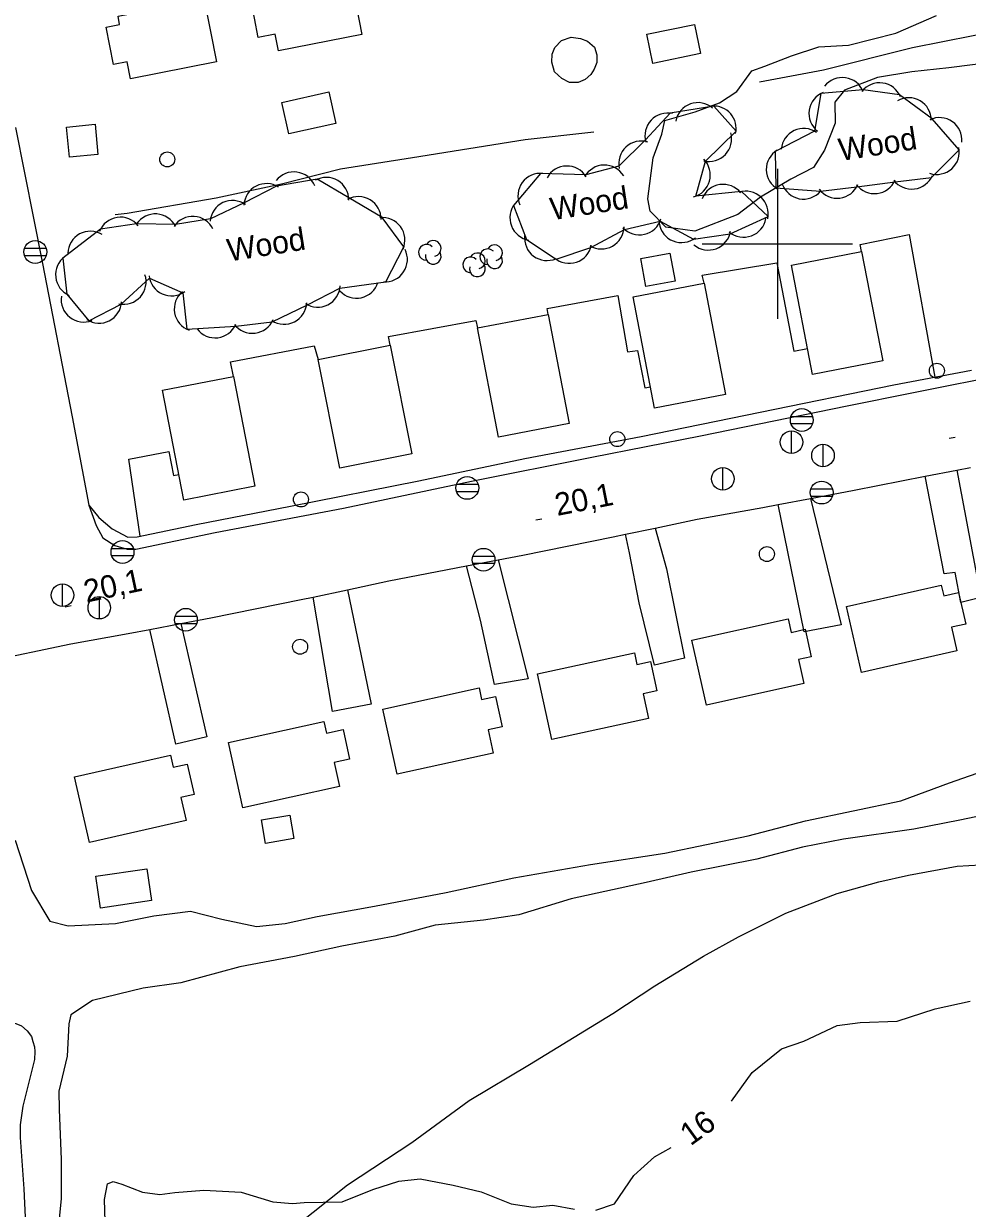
# Model space of a CAD drawing. Extents: x 646142 to 649934, y 5874075 to 5876351.
# Drawn here: x 646899.7 to 647025.3, y 5875071.6 to 5875229.3 of the extents above; entities that cross this region are included whole.
import ezdxf

# ---------------------------------------------------------------- set-up
doc = ezdxf.new("R2010")
doc.units = 0
for name, color, linetype in [('Niveau 1', 7, 'Continuous'), ('Niveau 19', 7, 'Continuous'), ('Niveau 2', 7, 'Continuous'), ('Niveau 21', 7, 'Continuous'), ('Niveau 22', 7, 'Continuous'), ('Niveau 3', 7, 'Continuous'), ('Niveau 31', 7, 'Continuous'), ('Niveau 36', 7, 'Continuous'), ('Niveau 4', 7, 'Continuous'), ('Niveau 44', 7, 'Continuous'), ('Niveau 61', 7, 'Continuous')]:
    doc.layers.add(name, color=color, linetype=linetype)

msp = doc.modelspace()

# ---------------------------------------------------------------- linework, layer by layer
at = {"layer": 'Niveau 1'}
for points in [[(647029.14, 5875224.24), (647022.82, 5875223.41), (647017.88, 5875222.92), (647013.33, 5875222.14), (647008.92, 5875220.45), (647007.66, 5875218.87), (647007.68, 5875216.07), (647006.29, 5875212.47), (647004.82, 5875210.18), (647001.78, 5875208.61), (646997.74, 5875206.22), (646994.72, 5875203.91), (646989, 5875201.67), (646985.16, 5875202.23), (646983.04, 5875204.37), (646982.75, 5875205.99), (646983.47, 5875211.45), (646984.62, 5875214.62), (646985, 5875216.44), (646989.06, 5875217.56), (646992.31, 5875218.76), (646994.61, 5875220.3), (646996.61, 5875223.01), (646998.32, 5875223.67), (647001.9, 5875225.02), (647005.5, 5875226.21), (647009.48, 5875226.47), (647015.79, 5875228.04), (647021.2, 5875230.42)], [(646898.52, 5875120.6), (646900.69, 5875113.91), (646903.14, 5875109.82), (646905.56, 5875109.21), (646911.89, 5875109.53), (646917, 5875110.56), (646921.86, 5875111.16), (646926.05, 5875110.08), (646930.63, 5875109.1), (646934.48, 5875109.52), (646938.73, 5875110.45), (646946.37, 5875111.84), (646955.91, 5875113.65), (646964.92, 5875115.62), (646975.1, 5875117.38), (646985.01, 5875118.89), (646996.1, 5875121.17), (647003.72, 5875123.19), (647016.42, 5875125.84), (647022.92, 5875128.24), (647028.37, 5875130.17)]]:
    msp.add_lwpolyline(points, dxfattribs=at)
at = {"layer": 'Niveau 19'}
for points in [[(647011.2, 5875198.98), (647011, 5875199.92), (647017.53, 5875201.24), (647020.94, 5875182.27)], [(646990.23, 5875194.75), (646989.97, 5875195.84), (646999.94, 5875197.47), (647002.21, 5875185.73), (647004.01, 5875186.07)], [(646969.5, 5875190.6), (646969.37, 5875191.4), (646978.75, 5875193.12), (646980.03, 5875185.62), (646981.37, 5875185.81), (646982.33, 5875180.84), (646983.09, 5875180.97)], [(646948.43, 5875186.51), (646948.21, 5875187.65), (646959.83, 5875189.79), (646960.09, 5875188.8)], [(646927.57, 5875182.36), (646927.17, 5875184.29), (646938.31, 5875186.44), (646938.88, 5875184.6)], [(646915.15, 5875161.07), (646913.67, 5875171.35), (646918.98, 5875172.34), (646919.61, 5875169.17), (646920.32, 5875169.28)], [(647023.9, 5875169.89), (647027.1, 5875152.94), (647024.43, 5875152.24), (647023.66, 5875156.25), (647022.19, 5875156.07), (647019.67, 5875169.06)], [(647004.4, 5875166.12), (647008.51, 5875149.28), (647003.57, 5875148.33), (647000.11, 5875165.31)], [(646983.72, 5875162.16), (646985.22, 5875156.75), (646987.65, 5875144.84), (646983.63, 5875143.89), (646981.59, 5875152.19), (646980.29, 5875158.88), (646979.76, 5875161.33)], [(646962.82, 5875157.94), (646966.83, 5875142.11), (646962.33, 5875141.33), (646960.49, 5875149.89), (646958.63, 5875157.14)], [(646942.78, 5875153.96), (646945.93, 5875138.71), (646940.77, 5875137.73), (646938.19, 5875152.98)], [(646920.56, 5875149.46), (646924.04, 5875134.36), (646919.91, 5875133.39), (646916.47, 5875148.68)], [(646897.27, 5875096.49), (646898.61, 5875096.2), (646899.37, 5875095.89), (646900.11, 5875095.25), (646900.68, 5875094.48), (646900.89, 5875093.83), (646901.11, 5875093.12), (646901.13, 5875092.5), (646901.1, 5875091.43), (646899.53, 5875085.21), (646899.17, 5875082.7), (646899.2, 5875081.01), (646899.68, 5875074.19), (646900.15, 5875063.78), (646900.5, 5875054.57), (646900.55, 5875049.06), (646899.93, 5875043.52), (646897.51, 5875037.07), (646896.53, 5875036.24), (646895.1, 5875035.55), (646893.95, 5875035.43), (646892.74, 5875035.5), (646891.78, 5875035.88), (646889.11, 5875036.54)]]:
    msp.add_lwpolyline(points, dxfattribs=at)
at = {"layer": 'Niveau 2'}
for points in [[(647028.54, 5875124.16), (647024.28, 5875123.27), (647018.18, 5875122.09), (647008.8, 5875120.76), (647003.33, 5875119.7), (646997.28, 5875118.07), (646988.51, 5875116.34), (646982.55, 5875115), (646972.55, 5875112.8), (646965.56, 5875110.67), (646960.87, 5875109.97), (646954.44, 5875109.28), (646949.09, 5875107.82), (646942.01, 5875106.49), (646935.73, 5875105.14), (646928.42, 5875103.73), (646920.56, 5875101.61), (646915.58, 5875100.89), (646908.81, 5875099.25), (646905.92, 5875097.35), (646905.65, 5875096.18)], [(646993.89, 5875085.87), (646996.64, 5875089.69), (647000.54, 5875092.83), (647003.52, 5875093.87), (647007.97, 5875095.95), (647011, 5875096.36), (647015.95, 5875096.5), (647015.95, 5875096.5), (647021.01, 5875098.17), (647025.67, 5875099.16)], [(646905.65, 5875096.18), (646905.65, 5875096.18), (646905.43, 5875091.87), (646904.33, 5875087.22), (646904.37, 5875084.77), (646904.64, 5875078.12), (646904.65, 5875072.87), (646904.21, 5875068.48)], [(646975.84, 5875071.36), (646978.32, 5875072.19), (646980.89, 5875075.99), (646983.64, 5875078.47), (646985.86, 5875079.69)], [(646910.55, 5875068.37), (646910.41, 5875072.78), (646910.82, 5875074.85), (646911.55, 5875075.19), (646912.74, 5875074.82), (646915.49, 5875073.75), (646917.77, 5875073.45), (646919.77, 5875073.72), (646923.62, 5875074.02), (646928.62, 5875073.76), (646932.84, 5875072.45), (646935.46, 5875072.24), (646937.01, 5875072.36), (646942.04, 5875072.45), (646946.12, 5875074.1), (646949.62, 5875075.24), (646952.43, 5875075.51), (646956.83, 5875074.68), (646960.55, 5875073.8), (646964.56, 5875072.19), (646967.48, 5875071.77), (646970.12, 5875072.03), (646973, 5875071.49)]]:
    msp.add_lwpolyline(points, dxfattribs=at)
at = {"layer": 'Niveau 21'}
for points in [[(646898.58, 5875215.49), (646902.17, 5875197.39), (646906.13, 5875176.95), (646908.33, 5875165.22), (646909.32, 5875162.49), (646910.19, 5875160.88), (646911.79, 5875159.82), (646913.45, 5875159.34), (646914.6, 5875159.37), (646925.14, 5875161.57), (646942.22, 5875164.82), (646959.27, 5875168.39), (646975.31, 5875171.62), (646989.78, 5875174.43), (647009.28, 5875178.42), (647018.14, 5875180.19), (647031.05, 5875182.78), (647032.82, 5875183.14), (647034.93, 5875183.52), (647046.52, 5875185.62), (647060.52, 5875188.37), (647071.67, 5875190.08), (647076.52, 5875190.67), (647093.72, 5875192.36)], [(646894.48, 5875144.34), (646905.94, 5875146.73), (646913.56, 5875148.12), (646916.47, 5875148.68), (646920.56, 5875149.46), (646924.57, 5875150.23), (646936.6, 5875152.64), (646938.19, 5875152.98), (646942.78, 5875153.96), (646948.28, 5875155.14), (646958.63, 5875157.14), (646962.82, 5875157.94), (646966.1, 5875158.57), (646978.12, 5875160.98), (646979.76, 5875161.33), (646983.72, 5875162.16), (646989.33, 5875163.33), (646998.07, 5875164.92), (647000.11, 5875165.31), (647004.4, 5875166.12), (647010.21, 5875167.22), (647019.67, 5875169.06), (647023.9, 5875169.89), (647025.73, 5875170.24)]]:
    msp.add_lwpolyline(points, dxfattribs=at)
at = {"layer": 'Niveau 22'}
for points in [[(646908.33, 5875165.22), (646909.66, 5875163.56), (646911.43, 5875162.06), (646913.51, 5875160.94), (646914.77, 5875160.98), (646922.62, 5875162.64), (646935.19, 5875165.09), (646952.26, 5875168.45), (646966.38, 5875171.44), (646981.88, 5875174.37), (646997.69, 5875177.57), (647015.5, 5875181.24), (647025.82, 5875183.19)], [(646935.81, 5875069.19), (646942.76, 5875074.73), (646951.32, 5875080.38), (646958.95, 5875085.96), (646967, 5875090.76), (646978.11, 5875097.53), (646983.7, 5875101.21), (646990.18, 5875105.18), (646994.82, 5875107.74), (647001.14, 5875110.89), (647007.96, 5875113.5), (647013.49, 5875115.08), (647017.46, 5875115.96), (647023.94, 5875117.15), (647030.14, 5875117.5)]]:
    msp.add_lwpolyline(points, dxfattribs=at)
at = {"layer": 'Niveau 3'}
for p, q in [((647022.87, 5875174.12), (647023.66, 5875174.27)), ((646967.85, 5875163.26), (646968.64, 5875163.41)), ((646905.18, 5875151.67), (646905.96, 5875151.84))]:
    msp.add_line(p, q, dxfattribs=at)
at = {"layer": 'Niveau 31'}
for points in [[(646944.67, 5875227.85), (646933.59, 5875225.69), (646933.15, 5875227.92), (646930.89, 5875227.48), (646929.88, 5875232.64), (646931.77, 5875233), (646931.55, 5875234.11), (646943.02, 5875236.33), (646944.67, 5875227.85)], [(646912.22, 5875230.32), (646923.69, 5875232.58), (646925.34, 5875224.23), (646913.88, 5875221.97), (646913.43, 5875224.25), (646911.6, 5875223.89), (646910.62, 5875228.86), (646912.43, 5875229.22), (646912.22, 5875230.32)], [(646982.61, 5875227.92), (646988.98, 5875229.21), (646989.77, 5875225.32), (646983.4, 5875224.02), (646982.61, 5875227.92)], [(646970.38, 5875226.12), (646971.24, 5875227.08), (646972.55, 5875227.51), (646973.77, 5875227.35), (646974.73, 5875226.97), (646975.63, 5875226.2), (646975.94, 5875225.17), (646975.95, 5875224.15), (646975.61, 5875223.25), (646975.15, 5875222.53), (646974.4, 5875221.87), (646973.48, 5875221.48), (646972.32, 5875221.5), (646971.3, 5875222.02), (646970.33, 5875222.89), (646969.95, 5875224.2), (646970.03, 5875225.27), (646970.38, 5875226.12), (646970.38, 5875226.12)], [(646934.02, 5875218.83), (646940.28, 5875220.23), (646941.21, 5875216.02), (646934.96, 5875214.63), (646934.02, 5875218.83)], [(646909.16, 5875215.91), (646909.54, 5875211.9), (646905.74, 5875211.54), (646905.36, 5875215.55), (646909.16, 5875215.91)], [(646981.83, 5875198.06), (646985.69, 5875198.76), (646986.37, 5875195.03), (646982.5, 5875194.32), (646981.83, 5875198.06)], [(647004.68, 5875182.6), (647001.86, 5875197.16), (647011.2, 5875198.98), (647014.02, 5875184.41), (647004.68, 5875182.6)], [(646983.64, 5875178.14), (646980.78, 5875192.93), (646990.23, 5875194.75), (646993.08, 5875179.96), (646983.64, 5875178.14)], [(646962.86, 5875174.27), (646960.09, 5875188.8), (646969.5, 5875190.6), (646972.28, 5875176.08), (646962.86, 5875174.27)], [(646941.76, 5875170.15), (646938.88, 5875184.6), (646948.43, 5875186.51), (646951.32, 5875172.06), (646941.76, 5875170.15)], [(646927.57, 5875182.36), (646930.42, 5875167.73), (646920.98, 5875165.89), (646918.13, 5875180.51), (646927.57, 5875182.36)], [(647009.21, 5875151.73), (647021.82, 5875154.58), (647022.15, 5875153.14), (647024.13, 5875153.58), (647025.08, 5875149.38), (647023.19, 5875148.95), (647023.9, 5875145.82), (647011.19, 5875142.94), (647009.21, 5875151.73)], [(646988.63, 5875147.23), (647001.42, 5875150.1), (647001.83, 5875148.28), (647003.68, 5875148.7), (647004.5, 5875145.04), (647002.83, 5875144.66), (647003.54, 5875141.49), (646990.57, 5875138.59), (646988.63, 5875147.23)], [(646968.05, 5875142.74), (646980.97, 5875145.57), (646981.3, 5875144.02), (646983.1, 5875144.41), (646983.96, 5875140.48), (646982.15, 5875140.08), (646982.86, 5875136.82), (646969.96, 5875134), (646968.05, 5875142.74)], [(646947.48, 5875138.06), (646960.29, 5875140.88), (646960.62, 5875139.34), (646962.49, 5875139.75), (646963.38, 5875135.71), (646961.49, 5875135.3), (646962.18, 5875132.19), (646949.39, 5875129.38), (646947.48, 5875138.06)], [(646926.93, 5875133.62), (646939.63, 5875136.43), (646939.97, 5875134.87), (646942.17, 5875135.36), (646943.04, 5875131.39), (646941, 5875130.94), (646941.7, 5875127.75), (646928.85, 5875124.91), (646926.93, 5875133.62)], [(646906.44, 5875129.04), (646919.2, 5875131.91), (646919.56, 5875130.33), (646921.42, 5875130.75), (646922.34, 5875126.68), (646920.58, 5875126.29), (646921.28, 5875123.22), (646908.41, 5875120.32), (646906.44, 5875129.04)], [(646931.31, 5875123.31), (646935.07, 5875123.94), (646935.6, 5875120.82), (646931.84, 5875120.19), (646931.31, 5875123.31)], [(646909.25, 5875115.81), (646916.06, 5875116.82), (646916.69, 5875112.57), (646909.88, 5875111.56), (646909.25, 5875115.81)]]:
    msp.add_lwpolyline(points, dxfattribs=at)
at = {"layer": 'Niveau 36'}
for p, q in [((646902.64, 5875199.37), (646899.76, 5875199.37)), ((646899.76, 5875198.45), (646902.64, 5875198.45)), ((647004.69, 5875176.99), (647001.81, 5875176.99)), ((647001.81, 5875176.07), (647004.69, 5875176.07)), ((647001.9, 5875172.08), (647001.9, 5875175.08)), ((647006.08, 5875170.31), (647006.08, 5875173.31)), ((646992.74, 5875167.22), (646992.74, 5875170.22)), ((646960.15, 5875167.96), (646957.27, 5875167.96)), ((646957.27, 5875167.04), (646960.15, 5875167.04)), ((647007.33, 5875167.34), (647004.45, 5875167.34)), ((647004.45, 5875166.42), (647007.33, 5875166.42)), ((646914.25, 5875159.42), (646911.37, 5875159.42)), ((646911.37, 5875158.5), (646914.25, 5875158.5)), ((646962.32, 5875158.39), (646959.44, 5875158.39)), ((646959.44, 5875157.47), (646962.32, 5875157.47)), ((646904.84, 5875151.73), (646904.84, 5875154.73)), ((646909.73, 5875150.05), (646909.73, 5875153.05)), ((646922.69, 5875150.4), (646919.81, 5875150.4)), ((646919.81, 5875149.48), (646922.69, 5875149.48))]:
    msp.add_line(p, q, dxfattribs=at)
for centre, radius in [((646918.77, 5875211.24), 1), ((646901.2, 5875198.92), 1.52), ((647021.23, 5875183.11), 1), ((647003.25, 5875176.54), 1.52), ((646978.69, 5875174), 1), ((647001.89, 5875173.59), 1.5), ((647006.07, 5875171.82), 1.5), ((646992.73, 5875168.73), 1.5), ((646958.71, 5875167.51), 1.52), ((647005.89, 5875166.89), 1.52), ((646936.57, 5875165.97), 1), ((646912.81, 5875158.97), 1.52), ((646960.88, 5875157.94), 1.52), ((646998.6, 5875158.7), 1), ((646904.83, 5875153.24), 1.5), ((646909.72, 5875151.56), 1.5), ((646921.25, 5875149.95), 1.52), ((646936.46, 5875146.37), 1)]:
    msp.add_circle(centre, radius, dxfattribs=at)
at = {"layer": 'Niveau 4'}
for points in [[(646997.61, 5875221.57), (647006.15, 5875223.18), (647017.99, 5875226.12), (647030.12, 5875228.52), (647037.36, 5875229.41), (647045.16, 5875229.33), (647056.59, 5875229.59), (647066.97, 5875230.06), (647076.56, 5875231.46), (647089.06, 5875232.42), (647101.26, 5875232.88), (647111.96, 5875233.39), (647117.73, 5875233.61)], [(646975.58, 5875214.86), (646966.4, 5875213.85), (646951.41, 5875211.45), (646941.82, 5875209.93), (646934, 5875207.94), (646925.26, 5875206.07), (646913.42, 5875204.05), (646911.83, 5875203.85)]]:
    msp.add_lwpolyline(points, dxfattribs=at)
at = {"layer": 'Niveau 44'}
for points in [[(646999.72, 5875212.3), (646999.8, 5875207.45), (647005.76, 5875207.02), (647010.58, 5875207.61), (647015.69, 5875208.24), (647020.5, 5875208.83), (647024.2, 5875212.53), (647020.6, 5875216.64), (647016.25, 5875219.85), (647011.44, 5875220.52), (647005.8, 5875220.03), (647004.95, 5875215), (646999.72, 5875212.3)], [(646968.46, 5875209.38), (646964.88, 5875205.11), (646966.6, 5875200.57), (646970.55, 5875197.95), (646975.15, 5875199.51), (646979.65, 5875201.92), (646984.38, 5875203.02), (646988.83, 5875200.64), (646993.7, 5875201.35), (646998.77, 5875203.65), (646995.21, 5875206.96), (646989.13, 5875206.34), (646990.41, 5875211.02), (646994.49, 5875215.01), (646991.54, 5875218.35), (646985.74, 5875217.39), (646982.43, 5875213.84), (646978.9, 5875210.33), (646974.51, 5875209.19), (646968.46, 5875209.38)], [(646904.88, 5875198.11), (646905.41, 5875193.28), (646908.33, 5875189.77), (646912.65, 5875191.97), (646916.39, 5875195.45), (646920.83, 5875193.47), (646921.38, 5875188.63), (646927.91, 5875189.04), (646932.73, 5875189.63), (646937.43, 5875191.9), (646941.76, 5875194.1), (646947.86, 5875194.94), (646950.27, 5875199.6), (646947.39, 5875203.51), (646942.93, 5875206.12), (646938.75, 5875208.59), (646933.33, 5875207.7), (646929.02, 5875205.48), (646924.52, 5875203.32), (646919.87, 5875202.57), (646914.69, 5875202.65), (646909.88, 5875201.94), (646904.88, 5875198.11)]]:
    msp.add_lwpolyline(points, dxfattribs=at)
for centre, radius, start, end in [((647008.65, 5875219.14), 3, 22.0122, 141.9901), ((647007.2, 5875217.37), 3, 111.7479, 231.7259), ((647013.6, 5875218.44), 3, 22.0122, 141.9901), ((646989.42, 5875215.8), 3, 49.4391, 169.417), ((647017.49, 5875216.45), 3, 359.9488, 119.9268), ((646985.37, 5875214.41), 3, 77.0005, 196.9785), ((646991.51, 5875215.35), 3, 347.3597, 93.9877), ((647003.51, 5875212.37), 3, 55.395, 175.3729), ((647021.58, 5875213.8), 3, 355.1187, 115.0966), ((646981.87, 5875210.69), 3, 72.8536, 192.8316), ((646990.91, 5875213.96), 3, 256.193, 16.1709), ((647001.52, 5875209.9), 3, 120.9705, 240.9484), ((647021.22, 5875212.24), 3, 251.5609, 11.5389), ((646988.07, 5875209.15), 3, 284.7659, 44.7439), ((646935.63, 5875206.58), 3, 22.0932, 142.0712), ((646968.45, 5875206.38), 3, 83.7193, 203.6972), ((646971.98, 5875207.36), 3, 31.4068, 151.3847), ((646976.98, 5875207.49), 3, 31.4068, 151.3847), ((647017.88, 5875210.29), 3, 217.0085, 336.9865), ((646931.98, 5875205.02), 3, 57.2693, 177.2472), ((646939.94, 5875205.84), 3, 359.3826, 119.3606), ((646992.78, 5875204.92), 3, 38.7348, 158.7127), ((647003.47, 5875208.96), 3, 199.4151, 319.393), ((647007.96, 5875209.07), 3, 217.0085, 336.9865), ((647012.92, 5875209.68), 3, 217.0085, 336.9865), ((646944.24, 5875203.29), 3, 359.3826, 119.3606), ((646995.79, 5875204.01), 3, 347.0452, 107.0232), ((646927.46, 5875202.77), 3, 55.2774, 175.2553), ((646967.39, 5875203.46), 3, 140.6498, 260.6277), ((646912.54, 5875200.55), 3, 38.3947, 158.3727), ((646917.18, 5875200.98), 3, 26.2958, 146.2737), ((646922.17, 5875200.65), 3, 26.2958, 146.2737), ((646947.41, 5875200.51), 3, 336.383, 96.361), ((646981.62, 5875204.19), 3, 223.1411, 343.1191), ((646987.22, 5875203.17), 3, 188.3985, 308.3764), ((646995.51, 5875203.89), 3, 230.1485, 350.1265), ((646908.53, 5875198.68), 3, 58.6014, 178.5794), ((646969.33, 5875200.78), 3, 173.3539, 293.3318), ((646976.58, 5875202.32), 3, 239.1042, 359.0821), ((646990.81, 5875202.17), 3, 230.1485, 350.1265), ((646953.28, 5875198.87), 1.05, 44.1154, 269.804), ((646954.18, 5875199.4), 1.05, 282.2692, 149.7263), ((646962.34, 5875198.81), 1.05, 282.2692, 149.7263), ((646972.28, 5875200.4), 3, 228.7427, 348.7206), ((646906.9, 5875195.89), 3, 126.2709, 246.2489), ((646947.74, 5875197.93), 3, 266.3372, 26.3151), ((646954.18, 5875198.35), 1.05, 166.9369, 29.6212), ((646959.16, 5875197.2), 1.05, 44.1154, 269.804), ((646960.06, 5875197.73), 1.05, 282.2692, 149.7263), ((646961.44, 5875198.28), 1.05, 44.1154, 269.804), ((646962.34, 5875197.76), 1.05, 166.9369, 29.6212), ((646960.06, 5875196.68), 1.05, 166.9369, 29.6212), ((646912.95, 5875194.95), 3, 258.3476, 18.3256), ((646919.33, 5875196.07), 3, 185.9832, 305.9612), ((646943.96, 5875195.76), 3, 222.4705, 342.4485), ((646922.7, 5875191.32), 3, 129.8546, 249.8325), ((646938.79, 5875194.57), 3, 237.0095, 356.9875), ((646907.64, 5875192.59), 3, 171.7759, 291.7539), ((646909.69, 5875192.44), 3, 237.0277, 357.0057), ((646934.34, 5875192.3), 3, 237.0095, 356.9875), ((646925.14, 5875190.48), 3, 217.0131, 336.9911), ((646930.1, 5875191.09), 3, 217.0131, 336.9911)]:
    msp.add_arc(centre, radius, start, end, dxfattribs=at)
at = {"layer": 'Niveau 61'}
for points in [[(647000, 5875210), (647000, 5875200), (647000, 5875190)], [(646990, 5875200), (647000, 5875200), (647010, 5875200)]]:
    msp.add_lwpolyline(points, dxfattribs=at)

# ---------------------------------------------------------------- texts
at = {"layer": 'Niveau 2'}
msp.add_text('16', height=3, rotation=35.8433, dxfattribs=at).set_placement((646988.43, 5875079.84))
at = {"layer": 'Niveau 3'}
for rotation, p in [(11.1525, (646970.69, 5875163.77)), (12.0513, (646908, 5875152.23))]:
    msp.add_text('20,1 ', height=3, rotation=rotation, dxfattribs=at).set_placement(p)
at = {"layer": 'Niveau 44'}
for p in [(647008.4, 5875211.01), (646970, 5875203.13), (646926.99, 5875197.64)]:
    msp.add_text('Wood', height=3, rotation=8.9405, dxfattribs=at).set_placement(p)

doc.saveas('drawing.dxf')
